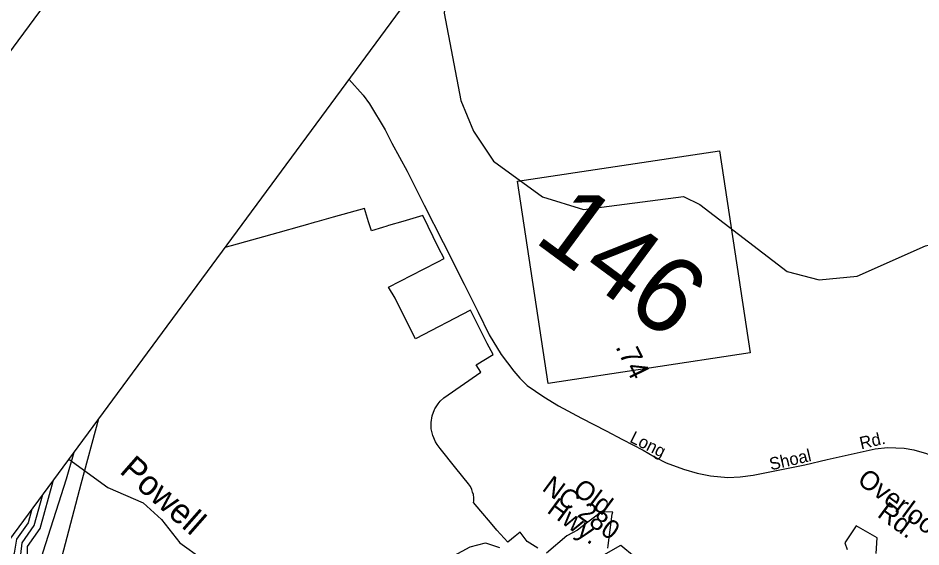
# Model space of a CAD drawing. Extents: x 945666 to 965748, y 644452 to 663300.
# Drawn here: x 952293 to 953003, y 659294 to 659710 of the extents above; entities that cross this region are included whole.
import ezdxf

# ---------------------------------------------------------------- set-up
doc = ezdxf.new("R2010")
doc.units = 0
for name, color, linetype in [('Exist Boundary Political City Limit New', 7, 'Continuous'), ('Exist Hydrographic Buffer Line', 7, 'Continuous'), ('Exist Hydrographic Creek Single Shore', 7, 'Continuous'), ('Exist Hydrographic Lake Shore', 7, 'Continuous'), ('Exist Hydrographic River Shore', 7, 'Continuous'), ('Exist Road Primary Interstate Divided Center Attributed', 7, 'Continuous'), ('Exist Road Primary NC Attributed', 7, 'Continuous'), ('Exist Road Primary NC Label', 7, 'Continuous'), ('Exist Road Primary NC Shield CELL', 7, 'Continuous'), ('Exist Road Primary NC Shield Number Label', 7, 'Continuous'), ('Exist Road Secondary Type 51 Label', 7, 'Continuous'), ('Old_Level_1', 7, 'Continuous'), ('Old_Level_49', 7, 'Continuous'), ('Prop Paved Shoulder', 7, 'Continuous'), ('Sheet Title CELL', 7, 'Continuous')]:
    doc.layers.add(name, color=color, linetype=linetype)

msp = doc.modelspace()

# ---------------------------------------------------------------- linework, layer by layer
at = {"layer": 'Exist Boundary Political City Limit New'}
for points in [[(952701.88, 659293.18), (952693.47, 659298.34), (952687.85, 659305.78), (952683.87, 659302.5), (952678.25, 659297.89), (952669.65, 659307.3), (952664.51, 659313.38), (952656.87, 659322.41), (952651.23, 659329.1), (952651.4, 659330.13), (952651.42, 659332.78), (952651.1, 659335.41), (952650.53, 659337.35), (952649.98, 659339.21), (952648.82, 659341.59), (952647.37, 659343.8), (952637.35, 659356.22), (952624.95, 659371.58), (952622.53, 659374.68), (952621.18, 659376.93), (952619.12, 659381.77), (952618.01, 659387.04), (952617.89, 659392.15), (952618.76, 659397.33), (952620.57, 659402.26), (952620.89, 659402.79), (952623.29, 659406.74), (952624.95, 659408.79), (952627.78, 659411.52), (952657.1, 659431.63), (952653.21, 659437.44), (952666.6, 659445.59), (952662.05, 659454.34), (952648.76, 659480.56), (952605.59, 659457.99), (952595.42, 659478.07), (952589.47, 659489.91), (952584.39, 659498.56), (952611.73, 659512.82), (952623.04, 659518.54), (952628.05, 659521.07), (952623.7, 659529.59), (952611.25, 659554.86), (952595.69, 659550.31), (952584.42, 659547.01), (952583.05, 659546.61), (952579.59, 659545.61), (952570.81, 659543.04), (952568.69, 659550.01), (952565.4, 659560.56), (952540.83, 659553.63), (952535.3, 659552.05), (952527.99, 659549.94), (952525.92, 659549.35), (952518.77, 659547.36), (952515.77, 659546.54), (952497.32, 659541.41), (952460.54, 659531.18), (952455.54, 659529.79)], [(952757.01, 659293.23), (952757.25, 659295.16), (952760.32, 659319.96), (952760.73, 659321.6), (952752.01, 659321.64), (952736.82, 659310.23), (952733.03, 659307.37), (952729.04, 659305.28), (952724.58, 659302.94), (952708.78, 659289.15)], [(952968.09, 659289.1), (952968.84, 659301.26), (952952.36, 659310.79), (952943.51, 659297.45), (952945.4, 659292.12)]]:
    msp.add_lwpolyline(points, dxfattribs=at)
at = {"layer": 'Exist Hydrographic Buffer Line'}
for points in [[(952295, 659288.27), (952295.93, 659297.32), (952305.44, 659310.93), (952312.26, 659335.51)], [(952303.65, 659323.84), (952300.66, 659313.18), (952291.67, 659300.3), (952289.8, 659289.19), (952256.45, 659197.69), (952253.89, 659189.58), (952244.73, 659160.52), (952237.25, 659118.34), (952230.74, 659047.88), (952209.95, 658984.08), (952190.16, 658857.04), (952176.24, 658754.09), (952172.26, 658687.49), (952179.19, 658625.55)]]:
    msp.add_lwpolyline(points, dxfattribs=at)
at = {"layer": 'Exist Hydrographic Creek Single Shore'}
for points in [[(952629.19, 659724.17), (952628.18, 659714.21), (952641.36, 659645.46), (952651.15, 659621.27), (952667.04, 659597.76), (952705.6, 659569.73), (952737.66, 659559.6), (952816.43, 659570), (952829.45, 659563.76), (952898.11, 659510.96), (952923.36, 659504.44), (952953.25, 659507.27), (953006.8, 659531.15), (953060.45, 659544.74), (953084.27, 659553.85), (953110.43, 659574.59), (953144.91, 659595.4), (953190.39, 659656.13), (953207.89, 659671.17), (953244.67, 659712.24), (953264.09, 659778.49), (953259.29, 659854.23)], [(952332.6, 659363.1), (952363.43, 659340.89), (952391.12, 659328.73), (952405.78, 659315.85), (952420.09, 659297.31), (952437.78, 659284.79), (952459.62, 659287.9), (952535.2, 659228.17), (952554.77, 659224.95), (952566.09, 659226.99)]]:
    msp.add_lwpolyline(points, dxfattribs=at)
at = {"layer": 'Exist Hydrographic Lake Shore'}
for points in [[(952616.68, 659276.81), (952648.54, 659294.25), (952660.64, 659297.31), (952671.62, 659293.7)], [(952731.73, 659275.44), (952767.1, 659295.56), (952777.99, 659286.65)]]:
    msp.add_lwpolyline(points, dxfattribs=at)
at = {"layer": 'Exist Hydrographic River Shore'}
msp.add_lwpolyline([(952190.58, 658617.15), (952182.63, 658686.88), (952186.54, 658752.7), (952200.43, 658855.45), (952219.84, 658980.86), (952240.98, 659045.77), (952247.49, 659116.59), (952254.31, 659156.5), (952268.31, 659189.83), (952266.21, 659194.13), (952300.2, 659287.35), (952300.19, 659294.35), (952310.21, 659308.69), (952320.45, 659345.96), (952321.5, 659348.05)], dxfattribs=at)
at = {"layer": 'Exist Road Primary Interstate Divided Center Attributed'}
for points in [[(952218.29, 658596.72), (952220.44, 658613.7), (952228.12, 658689.95), (952243.24, 658837.53), (952254.14, 658963.62), (952258.26, 658998.75), (952267.23, 659049.19), (952295.78, 659165.98), (952342.48, 659343.91), (952356.23, 659395.14)], [(952336.65, 659368.59), (952330.58, 659347.56), (952312.18, 659290.03), (952295.46, 659230.61), (952272.27, 659149.42), (952256.21, 659087.83), (952244.09, 659032.36), (952239.92, 659005.62), (952235.48, 658965.71), (952215.32, 658767.01), (952200.36, 658609.94)]]:
    msp.add_lwpolyline(points, dxfattribs=at)
at = {"layer": 'Exist Road Primary NC Attributed'}
for points in [[(952553.21, 659662.22), (952564.26, 659649.71), (952569.31, 659642.79), (952581.76, 659622.5), (952586.94, 659611.8), (952599.08, 659589.77), (952612.28, 659563.14), (952627.25, 659533.65), (952643.86, 659500.92), (952654.99, 659478.96), (952663.56, 659461.05), (952672.87, 659445.55), (952682.83, 659432.45), (952687.78, 659426.96), (952693.47, 659421.25), (952706.44, 659412.32), (952718.11, 659405.23), (952736.19, 659395.5), (952755.7, 659385.42), (952768.43, 659378.68), (952784.66, 659370.31), (952793.62, 659365.08), (952802.93, 659360.2)], [(952802.93, 659360.2), (952816.47, 659355.26), (952827.14, 659352.27), (952837.67, 659350.02), (952851.31, 659348.9), (952861.18, 659349.38), (952871.22, 659350.53), (952911.94, 659358.87), (952929.5, 659362.86), (952967.44, 659371.32), (952976.92, 659372.41), (952990.08, 659371.89), (952997.72, 659370.65), (953007.62, 659367.76), (953016.38, 659363.93), (953024.18, 659358.9), (953034.59, 659351.38), (953044.23, 659342.35), (953053.63, 659332.58)]]:
    msp.add_lwpolyline(points, dxfattribs=at)
at = {"layer": 'Exist Road Primary NC Shield CELL'}
msp.add_lwpolyline([(952685.92, 659581.9), (952844.92, 659605.92), (952868.95, 659446.91), (952709.94, 659422.89)], close=True, dxfattribs=at)
at = {"layer": 'Old_Level_1'}
msp.add_lwpolyline([(953667.37, 661172.93), (956829.74, 658840.64), (955088.61, 656479.82), (951926.24, 658812.1)], close=True, dxfattribs=at)
at = {"layer": 'Sheet Title CELL'}
msp.add_line((948788.22, 654940.68), (953744.35, 661660.75), dxfattribs=at)

# ---------------------------------------------------------------- texts
at = {"layer": 'Exist Road Primary NC Label'}
for s, rotation, p in [('Long', 333.68455, (952773.47, 659377.02)), ('Rd.', 13.11831, (952956.3, 659370.88)), ('Shoal', 13.11831, (952885.29, 659354.34))]:
    msp.add_text(s, height=9.743, rotation=rotation, dxfattribs=at).set_placement(p)
at = {"layer": 'Exist Road Primary NC Shield Number Label'}
msp.add_text('146', height=59.759, rotation=323.59084, dxfattribs=at).set_placement((952697.72, 659535.13))
at = {"layer": 'Exist Road Secondary Type 51 Label'}
for s, p in [('Overlook', (952952.35, 659344.86)), ('NC 280', (952704.4, 659339.15)), ('Old', (952728.42, 659336.92)), ('Hwy.', (952708.23, 659321.73)), ('Rd.', (952968.2, 659318.53))]:
    msp.add_text(s, height=15, rotation=323.59084, dxfattribs=at).set_placement(p)
at = {"layer": 'Old_Level_49'}
msp.add_text('.74', height=16.238, rotation=295.99715, dxfattribs=at).set_placement((952762.67, 659451.69))
at = {"layer": 'Prop Paved Shoulder'}
msp.add_text('Powell', height=19.486, rotation=318.67799, dxfattribs=at).set_placement((952371.84, 659352.96))
at = {"layer": 'Sheet Title CELL'}
msp.add_text('TIP PROJECT:', height=249.9998, rotation=53.59084, dxfattribs=at).set_placement((951327.58, 658659.91))

doc.saveas('drawing.dxf')
